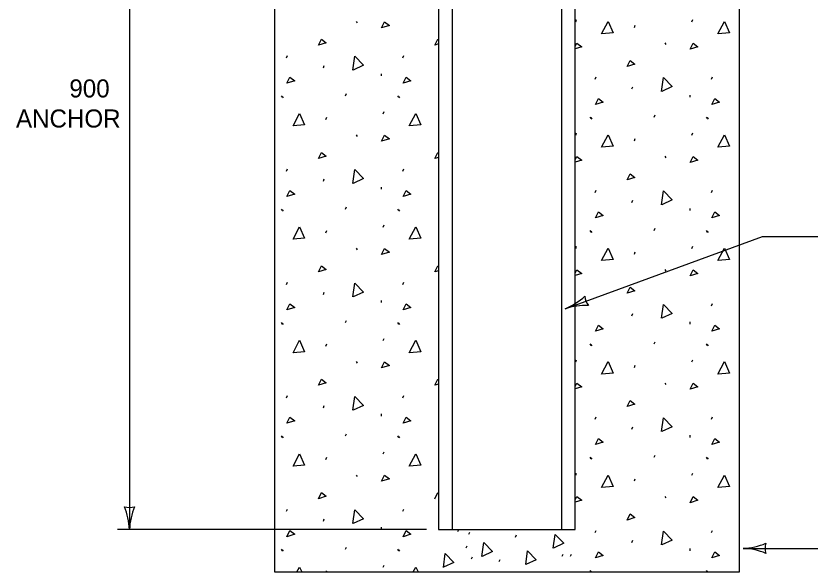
# Model space of a CAD drawing. Extents: x 49940 to 50043, y 49986 to 50011.
# Drawn here: x 50026.445 to 50029.111, y 49990.668 to 49992.517 of the extents above; entities that cross this region are included whole.
import ezdxf

# ---------------------------------------------------------------- set-up
doc = ezdxf.new("R2010")
doc.units = 0
for name, color, linetype in [('Level 1', 7, 'Continuous'), ('Level 2', 7, 'Continuous'), ('Level 3', 7, 'Continuous'), ('Level 4', 7, 'Continuous')]:
    doc.layers.add(name, color=color, linetype=linetype)

msp = doc.modelspace()

# ---------------------------------------------------------------- linework, layer by layer
at = {"layer": 'Level 1'}
for p, q in [((50027.3049, 49993.3945), (50027.3049, 49990.6682)), ((50028.8498, 49990.6682), (50028.8498, 49993.3945)), ((50027.5759, 49992.4984), (50027.5791, 49992.4935)), ((50028.3057, 49992.4976), (50028.3087, 49992.5049)), ((50028.692, 49992.4976), (50028.6953, 49992.5049)), ((50028.5009, 49992.479), (50028.504, 49992.4863)), ((50028.6018, 49992.4275), (50028.6049, 49992.4225)), ((50027.3442, 49992.3781), (50027.3474, 49992.3853)), ((50027.7307, 49992.3781), (50027.734, 49992.3853)), ((50027.4669, 49992.3449), (50027.47, 49992.3522)), ((50027.6587, 49992.3248), (50027.6594, 49992.3174)), ((50028.3702, 49992.3072), (50028.3734, 49992.3145)), ((50028.7567, 49992.3072), (50028.76, 49992.3145)), ((50028.4928, 49992.2741), (50028.4959, 49992.2814)), ((50027.3272, 49992.2513), (50027.3305, 49992.2466)), ((50027.5402, 49992.2513), (50027.5435, 49992.2586)), ((50027.7137, 49992.2513), (50027.7171, 49992.2466)), ((50028.6847, 49992.2538), (50028.6854, 49992.2466)), ((50027.3305, 49992.2495), (50027.3338, 49992.2447)), ((50027.7171, 49992.2495), (50027.7203, 49992.2447)), ((50027.6661, 49992.1916), (50027.6694, 49992.1988)), ((50027.4749, 49992.173), (50027.4782, 49992.1802)), ((50028.3532, 49992.1805), (50028.3564, 49992.1757)), ((50028.3564, 49992.1787), (50028.3596, 49992.1739)), ((50028.5662, 49992.1805), (50028.5695, 49992.1879)), ((50028.7397, 49992.1805), (50028.7429, 49992.1757)), ((50028.7429, 49992.1787), (50028.7462, 49992.1739)), ((50027.5759, 49992.1214), (50027.5791, 49992.1164)), ((50028.3057, 49992.1207), (50028.3087, 49992.1279)), ((50028.692, 49992.1207), (50028.6953, 49992.1279)), ((50028.5009, 49992.1021), (50028.504, 49992.1094)), ((50028.6018, 49992.0505), (50028.6049, 49992.0456)), ((50027.3442, 49992.0011), (50027.3474, 49992.0084)), ((50027.7307, 49992.0011), (50027.734, 49992.0084)), ((50027.4669, 49991.968), (50027.47, 49991.9753)), ((50027.6587, 49991.9478), (50027.6594, 49991.9405)), ((50028.3702, 49991.9301), (50028.3734, 49991.9375)), ((50028.7567, 49991.9301), (50028.76, 49991.9375)), ((50028.4928, 49991.8971), (50028.4959, 49991.9044)), ((50027.5402, 49991.8745), (50027.5435, 49991.8817)), ((50028.6847, 49991.8769), (50028.6854, 49991.8697)), ((50027.3272, 49991.8745), (50027.3305, 49991.8697)), ((50027.3305, 49991.8726), (50027.3338, 49991.8679)), ((50027.7137, 49991.8745), (50027.7171, 49991.8697)), ((50027.7171, 49991.8726), (50027.7203, 49991.8679)), ((50027.4749, 49991.7961), (50027.4782, 49991.8033)), ((50027.6661, 49991.8146), (50027.6694, 49991.8219)), ((50028.3532, 49991.8035), (50028.3564, 49991.7985)), ((50028.3564, 49991.8017), (50028.3596, 49991.7968)), ((50028.5662, 49991.8035), (50028.5695, 49991.8108)), ((50028.7397, 49991.8035), (50028.7429, 49991.7985)), ((50028.7429, 49991.8017), (50028.7462, 49991.7968)), ((50027.5759, 49991.7445), (50027.5791, 49991.7396)), ((50028.3057, 49991.7437), (50028.3087, 49991.7509)), ((50028.692, 49991.7437), (50028.6953, 49991.7509)), ((50028.5009, 49991.7251), (50028.504, 49991.7324)), ((50028.6018, 49991.6734), (50028.6049, 49991.6686)), ((50027.3442, 49991.624), (50027.3474, 49991.6314)), ((50027.7307, 49991.624), (50027.734, 49991.6314)), ((50027.4669, 49991.5911), (50027.47, 49991.5984)), ((50027.6587, 49991.5708), (50027.6594, 49991.5637)), ((50028.7567, 49991.5533), (50028.76, 49991.5605)), ((50027.5402, 49991.4974), (50027.5435, 49991.5047)), ((50028.4928, 49991.5202), (50028.4959, 49991.5276)), ((50027.3272, 49991.4974), (50027.3305, 49991.4926)), ((50027.3305, 49991.4956), (50027.3338, 49991.4907)), ((50027.7137, 49991.4974), (50027.7171, 49991.4926)), ((50027.7171, 49991.4956), (50027.7203, 49991.4907)), ((50028.6847, 49991.4999), (50028.6854, 49991.4926)), ((50027.4749, 49991.419), (50027.4782, 49991.4263)), ((50027.6661, 49991.4377), (50027.6694, 49991.4449)), ((50028.3532, 49991.4267), (50028.3564, 49991.4216)), ((50028.3564, 49991.4246), (50028.3596, 49991.4198)), ((50028.5662, 49991.4267), (50028.5695, 49991.4339)), ((50028.7397, 49991.4267), (50028.7429, 49991.4216)), ((50028.7429, 49991.4246), (50028.7462, 49991.4198)), ((50028.3057, 49991.3667), (50028.3087, 49991.374)), ((50028.692, 49991.3667), (50028.6953, 49991.374)), ((50027.5759, 49991.3675), (50027.5791, 49991.3626)), ((50028.5009, 49991.3482), (50028.504, 49991.3554)), ((50028.6018, 49991.2964), (50028.6049, 49991.2917)), ((50027.3442, 49991.2472), (50027.3474, 49991.2545)), ((50027.7307, 49991.2472), (50027.734, 49991.2545)), ((50027.4669, 49991.2141), (50027.47, 49991.2214)), ((50027.6587, 49991.1938), (50027.6594, 49991.1865)), ((50028.3702, 49991.1763), (50028.3734, 49991.1836)), ((50028.7567, 49991.1763), (50028.76, 49991.1836)), ((50028.4928, 49991.1433), (50028.4959, 49991.1505)), ((50027.3272, 49991.1205), (50027.3305, 49991.1157)), ((50027.3305, 49991.1187), (50027.3338, 49991.1137)), ((50027.5402, 49991.1205), (50027.5435, 49991.1278)), ((50027.7137, 49991.1205), (50027.7171, 49991.1157)), ((50027.7171, 49991.1187), (50027.7203, 49991.1137)), ((50028.6847, 49991.1228), (50028.6854, 49991.1158)), ((50027.6661, 49991.0606), (50027.6694, 49991.0679)), ((50028.5662, 49991.0496), (50028.5695, 49991.0569)), ((50027.4749, 49991.0421), (50027.4782, 49991.0494)), ((50028.3532, 49991.0496), (50028.3564, 49991.0447)), ((50028.3564, 49991.0478), (50028.3596, 49991.0428)), ((50028.7397, 49991.0496), (50028.7429, 49991.0447)), ((50028.7429, 49991.0478), (50028.7462, 49991.0428)), ((50027.5759, 49990.9905), (50027.5791, 49990.9857)), ((50028.3057, 49990.9896), (50028.3087, 49990.9971)), ((50028.5009, 49990.9712), (50028.504, 49990.9784)), ((50028.692, 49990.9896), (50028.6953, 49990.9971)), ((50028.6018, 49990.9196), (50028.6049, 49990.9147)), ((50027.3442, 49990.8702), (50027.3474, 49990.8774)), ((50027.7307, 49990.8702), (50027.734, 49990.8774)), ((50027.4669, 49990.8372), (50027.47, 49990.8444)), ((50027.6587, 49990.8168), (50027.6594, 49990.8096)), ((50027.8502, 49990.8092), (50028.3045, 49990.8092)), ((50027.9142, 49990.8026), (50027.9173, 49990.8097)), ((50027.9506, 49990.7934), (50027.9539, 49990.8006)), ((50028.1056, 49990.7843), (50028.1088, 49990.7915)), ((50028.3702, 49990.7993), (50028.3734, 49990.8065)), ((50028.7567, 49990.7993), (50028.76, 49990.8065)), ((50028.4928, 49990.7663), (50028.4959, 49990.7735)), ((50027.3272, 49990.7435), (50027.3305, 49990.7387)), ((50027.3305, 49990.7417), (50027.3338, 49990.7368)), ((50027.5402, 49990.7435), (50027.5435, 49990.7508)), ((50027.7137, 49990.7435), (50027.7171, 49990.7387)), ((50027.7171, 49990.7417), (50027.7203, 49990.7368)), ((50027.9416, 49990.748), (50027.9448, 49990.7552)), ((50028.6847, 49990.7459), (50028.6854, 49990.7387)), ((50027.9598, 49990.7116), (50027.963, 49990.7188)), ((50028.051, 49990.7025), (50028.0542, 49990.7098)), ((50028.2609, 49990.7208), (50028.264, 49990.7279)), ((50028.2881, 49990.7208), (50028.2914, 49990.7279)), ((50027.6661, 49990.6836), (50027.6694, 49990.6911)), ((50027.3049, 49990.6682), (50028.8498, 49990.6682)), ((50027.4762, 49990.6682), (50027.4782, 49990.6725)), ((50028.3532, 49990.6727), (50028.3562, 49990.6682)), ((50028.3564, 49990.6709), (50028.3581, 49990.6682)), ((50028.7397, 49990.6727), (50028.7427, 49990.6682)), ((50028.7429, 49990.6709), (50028.7446, 49990.6682))]:
    msp.add_line(p, q, dxfattribs=at)
for points in [[(50028.3045, 49990.8092), (50028.3045, 49993.6425), (50027.8502, 49993.6425), (50027.8502, 49990.8092)], [(50027.6605, 49992.4773), (50027.6702, 49992.4976), (50027.6863, 49992.4856), (50027.6605, 49992.4773)], [(50028.3919, 49992.4572), (50028.4137, 49992.4986), (50028.4306, 49992.4605), (50028.3926, 49992.4572)], [(50028.7785, 49992.4572), (50028.8003, 49992.4986), (50028.8172, 49992.4605), (50028.7793, 49992.4572)], [(50027.4508, 49992.4196), (50027.4606, 49992.4399), (50027.4767, 49992.4277), (50027.4508, 49992.4196)], [(50027.8375, 49992.4196), (50027.8471, 49992.4399), (50027.8502, 49992.4376)], [(50027.8502, 49992.4237), (50027.8375, 49992.4196)], [(50028.3045, 49992.4163), (50028.3095, 49992.4267), (50028.3257, 49992.4145), (50028.3045, 49992.4079)], [(50028.6865, 49992.4064), (50028.6961, 49992.4267), (50028.7123, 49992.4145), (50028.6865, 49992.4064)], [(50027.565, 49992.3367), (50027.5715, 49992.3827), (50027.6003, 49992.3529), (50027.5658, 49992.3369)], [(50028.4768, 49992.3488), (50028.4865, 49992.3691), (50028.5026, 49992.3568), (50028.4768, 49992.3488)], [(50027.3458, 49992.2933), (50027.3555, 49992.3134), (50027.3716, 49992.3014), (50027.3458, 49992.2933)], [(50027.7324, 49992.2933), (50027.7422, 49992.3134), (50027.7581, 49992.3014), (50027.7324, 49992.2933)], [(50028.591, 49992.2657), (50028.5974, 49992.3117), (50028.6263, 49992.282), (50028.5919, 49992.266)], [(50028.3717, 49992.2224), (50028.3813, 49992.2426), (50028.3976, 49992.2305), (50028.3717, 49992.2224)], [(50028.7583, 49992.2224), (50028.768, 49992.2426), (50028.7841, 49992.2305), (50028.7583, 49992.2224)], [(50027.3661, 49992.1513), (50027.3878, 49992.1924), (50027.4048, 49992.1545), (50027.3668, 49992.1513)], [(50027.7525, 49992.1513), (50027.7744, 49992.1924), (50027.7912, 49992.1545), (50027.7533, 49992.1513)], [(50027.6605, 49992.1003), (50027.6702, 49992.1206), (50027.6863, 49992.1085), (50027.6605, 49992.1003)], [(50028.3919, 49992.0803), (50028.4137, 49992.1215), (50028.4306, 49992.0836), (50028.3926, 49992.0803)], [(50028.7785, 49992.0803), (50028.8003, 49992.1215), (50028.8172, 49992.0836), (50028.7793, 49992.0803)], [(50027.4508, 49992.0427), (50027.4606, 49992.0629), (50027.4767, 49992.0508), (50027.4508, 49992.0427)], [(50027.8375, 49992.0427), (50027.8471, 49992.0629), (50027.8502, 49992.0605)], [(50027.8502, 49992.0467), (50027.8375, 49992.0427)], [(50028.3045, 49992.0393), (50028.3095, 49992.0497), (50028.3257, 49992.0375), (50028.3045, 49992.0309)], [(50028.6865, 49992.0295), (50028.6961, 49992.0497), (50028.7123, 49992.0375), (50028.6865, 49992.0295)], [(50027.565, 49991.9597), (50027.5715, 49992.0058), (50027.6003, 49991.976), (50027.5658, 49991.96)], [(50028.4768, 49991.9718), (50028.4865, 49991.992), (50028.5026, 49991.9799), (50028.4768, 49991.9718)], [(50027.3458, 49991.9164), (50027.3555, 49991.9365), (50027.3716, 49991.9246), (50027.3458, 49991.9164)], [(50027.7324, 49991.9164), (50027.7422, 49991.9365), (50027.7581, 49991.9246), (50027.7324, 49991.9164)], [(50028.591, 49991.8888), (50028.5974, 49991.935), (50028.6263, 49991.9052), (50028.5919, 49991.8891)], [(50028.3717, 49991.8455), (50028.3813, 49991.8657), (50028.3976, 49991.8535), (50028.3717, 49991.8455)], [(50028.7583, 49991.8455), (50028.768, 49991.8657), (50028.7841, 49991.8535), (50028.7583, 49991.8455)], [(50027.3661, 49991.7743), (50027.3878, 49991.8154), (50027.4048, 49991.7776), (50027.3668, 49991.7743)], [(50027.7525, 49991.7743), (50027.7744, 49991.8154), (50027.7912, 49991.7776), (50027.7533, 49991.7743)], [(50027.6605, 49991.7233), (50027.6702, 49991.7436), (50027.6863, 49991.7315), (50027.6605, 49991.7233)], [(50028.3919, 49991.7033), (50028.4137, 49991.7445), (50028.4306, 49991.7066), (50028.3926, 49991.7033)], [(50028.7785, 49991.7033), (50028.8003, 49991.7445), (50028.8172, 49991.7066), (50028.7793, 49991.7033)], [(50027.4508, 49991.6657), (50027.4606, 49991.6859), (50027.4767, 49991.6738), (50027.4508, 49991.6657)], [(50027.8375, 49991.6657), (50027.8471, 49991.6859), (50027.8502, 49991.6836)], [(50027.8502, 49991.6698), (50027.8375, 49991.6657)], [(50028.3045, 49991.6622), (50028.3095, 49991.6727), (50028.3257, 49991.6606), (50028.3045, 49991.6539)], [(50028.6865, 49991.6525), (50028.6961, 49991.6727), (50028.7123, 49991.6606), (50028.6865, 49991.6525)], [(50027.565, 49991.5828), (50027.5715, 49991.6289), (50027.6003, 49991.599), (50027.5658, 49991.583)], [(50028.4768, 49991.5949), (50028.4865, 49991.615), (50028.5026, 49991.603), (50028.4768, 49991.5949)], [(50027.3458, 49991.5393), (50027.3555, 49991.5596), (50027.3716, 49991.5475), (50027.3458, 49991.5393)], [(50027.7324, 49991.5393), (50027.7422, 49991.5596), (50027.7581, 49991.5475), (50027.7324, 49991.5393)], [(50028.591, 49991.5119), (50028.5974, 49991.558), (50028.6263, 49991.5281), (50028.5919, 49991.5121)], [(50028.3717, 49991.4685), (50028.3813, 49991.4887), (50028.3976, 49991.4766), (50028.3717, 49991.4685)], [(50028.7583, 49991.4685), (50028.768, 49991.4887), (50028.7841, 49991.4766), (50028.7583, 49991.4685)], [(50027.3661, 49991.3973), (50027.3878, 49991.4385), (50027.4048, 49991.4005), (50027.3668, 49991.3973)], [(50027.7525, 49991.3973), (50027.7744, 49991.4385), (50027.7912, 49991.4005), (50027.7533, 49991.3973)], [(50027.6605, 49991.3465), (50027.6702, 49991.3667), (50027.6863, 49991.3546), (50027.6605, 49991.3465)], [(50028.3919, 49991.3263), (50028.4137, 49991.3675), (50028.4306, 49991.3297), (50028.3926, 49991.3263)], [(50028.7785, 49991.3263), (50028.8003, 49991.3675), (50028.8172, 49991.3297), (50028.7793, 49991.3263)], [(50027.4508, 49991.2888), (50027.4606, 49991.3089), (50027.4767, 49991.2969), (50027.4508, 49991.2888)], [(50027.8375, 49991.2888), (50027.8471, 49991.3089), (50027.8502, 49991.3067)], [(50027.8502, 49991.2927), (50027.8375, 49991.2888)], [(50028.3045, 49991.2853), (50028.3095, 49991.2957), (50028.3257, 49991.2836), (50028.3045, 49991.277)], [(50028.6865, 49991.2756), (50028.6961, 49991.2957), (50028.7123, 49991.2836), (50028.6865, 49991.2756)], [(50027.565, 49991.2058), (50027.5715, 49991.252), (50027.6003, 49991.222), (50027.5658, 49991.2061)], [(50028.4768, 49991.2179), (50028.4865, 49991.2381), (50028.5026, 49991.2259), (50028.4768, 49991.2179)], [(50027.3458, 49991.1624), (50027.3555, 49991.1827), (50027.3716, 49991.1705), (50027.3458, 49991.1624)], [(50027.7324, 49991.1624), (50027.7422, 49991.1827), (50027.7581, 49991.1705), (50027.7324, 49991.1624)], [(50028.591, 49991.1349), (50028.5974, 49991.1809), (50028.6263, 49991.1511), (50028.5919, 49991.1352)], [(50028.3717, 49991.0915), (50028.3813, 49991.1118), (50028.3976, 49991.0996), (50028.3717, 49991.0915)], [(50028.7583, 49991.0915), (50028.768, 49991.1118), (50028.7841, 49991.0996), (50028.7583, 49991.0915)], [(50027.3661, 49991.0203), (50027.3878, 49991.0614), (50027.4048, 49991.0236), (50027.3668, 49991.0203)], [(50027.7525, 49991.0203), (50027.7744, 49991.0614), (50027.7912, 49991.0236), (50027.7533, 49991.0203)], [(50027.6605, 49990.9696), (50027.6702, 49990.9896), (50027.6863, 49990.9775), (50027.6605, 49990.9696)], [(50028.3919, 49990.9495), (50028.4137, 49990.9905), (50028.4306, 49990.9527), (50028.3926, 49990.9495)], [(50028.7785, 49990.9495), (50028.8003, 49990.9905), (50028.8172, 49990.9527), (50028.7793, 49990.9495)], [(50027.4508, 49990.9118), (50027.4606, 49990.9319), (50027.4767, 49990.9198), (50027.4508, 49990.9118)], [(50027.8375, 49990.9118), (50027.8471, 49990.9319), (50027.8502, 49990.9296)], [(50028.3045, 49990.9082), (50028.3095, 49990.9188), (50028.3257, 49990.9067), (50028.3045, 49990.9001)], [(50028.6865, 49990.8986), (50028.6961, 49990.9188), (50028.7123, 49990.9067), (50028.6865, 49990.8986)], [(50027.565, 49990.8288), (50027.5715, 49990.8749), (50027.6003, 49990.845), (50027.5658, 49990.829)], [(50028.4768, 49990.8409), (50028.4865, 49990.8611), (50028.5026, 49990.849), (50028.4768, 49990.8409)], [(50027.3458, 49990.7855), (50027.3555, 49990.8057), (50027.3716, 49990.7936), (50027.3458, 49990.7855)], [(50027.7324, 49990.7855), (50027.7422, 49990.8057), (50027.7581, 49990.7936), (50027.7324, 49990.7855)], [(50028.2308, 49990.7471), (50028.2371, 49990.7932), (50028.2661, 49990.7634), (50028.2316, 49990.7473)], [(50028.591, 49990.7579), (50028.5974, 49990.8041), (50028.6263, 49990.7742), (50028.5919, 49990.7582)], [(50027.9936, 49990.7197), (50028, 49990.7659), (50028.0289, 49990.7361), (50027.9944, 49990.7201)], [(50028.1395, 49990.6925), (50028.146, 49990.7386), (50028.1749, 49990.7088), (50028.1403, 49990.6928)], [(50028.3717, 49990.7147), (50028.3813, 49990.7347), (50028.3976, 49990.7226), (50028.3717, 49990.7147)], [(50028.7583, 49990.7147), (50028.768, 49990.7347), (50028.7841, 49990.7226), (50028.7583, 49990.7147)], [(50027.8659, 49990.6834), (50027.8724, 49990.7295), (50027.9012, 49990.6997), (50027.8668, 49990.6836)], [(50027.3792, 49990.6682), (50027.3878, 49990.6845), (50027.3951, 49990.6682)], [(50027.7658, 49990.6682), (50027.7744, 49990.6845), (50027.7816, 49990.6682)]]:
    msp.add_lwpolyline(points, dxfattribs=at)
at = {"layer": 'Level 3'}
for p, q in [((50026.8225, 49993.6425), (50026.8225, 49990.8092)), ((50028.2709, 49991.5434), (50028.9266, 49991.7833)), ((50028.9266, 49991.7833), (50029.1111, 49991.7833)), ((50027.8102, 49990.8092), (50026.7825, 49990.8092)), ((50028.862, 49990.7467), (50029.1111, 49990.7467))]:
    msp.add_line(p, q, dxfattribs=at)
for centre, radius, start, end in [((50028.1801, 49991.758), 0.233, 292.9233, 312.1731), ((50028.3913, 49991.5875), 0.0548, 182.2348, 217.9572), ((50028.3386, 49991.3316), 0.2223, 87.552, 107.7355), ((50026.8225, 49990.9374), 0.0548, 252.1388, 287.8612), ((50026.5898, 49990.7977), 0.233, 2.8273, 22.0772), ((50027.0446, 49990.8), 0.2223, 157.456, 177.6395), ((50028.8505, 49990.9794), 0.233, 272.8273, 292.0772), ((50028.9902, 49990.7467), 0.0548, 162.1388, 197.8612), ((50028.8528, 49990.5246), 0.2223, 67.456, 87.6395)]:
    msp.add_arc(centre, radius, start, end, dxfattribs=at)
at = {"layer": 'Level 4'}
for p, q in [((50027.8963, 49990.8092), (50027.8963, 49993.6425)), ((50028.2596, 49990.8092), (50028.2596, 49993.6425))]:
    msp.add_line(p, q, dxfattribs=at)

# ---------------------------------------------------------------- texts
at = {"layer": 'Level 2'}
for s, p in [('900', (50026.6226, 49992.2459)), ('ANCHOR', (50026.4452, 49992.1459))]:
    msp.add_text(s, height=0.06, dxfattribs=at).set_placement(p)

doc.saveas('drawing.dxf')
